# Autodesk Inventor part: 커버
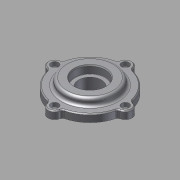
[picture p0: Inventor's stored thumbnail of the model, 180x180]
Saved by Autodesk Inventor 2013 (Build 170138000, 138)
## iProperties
Company: 한국ATC센터
Created: 2015-12
Part Number: 커버
Document SubType Name: Modeling
Designer: mdu
Density: 1 g/cm^3
Material: 일반
Mass: 49.9044 g
Surface Area: 145.431 cm^2
Volume: 49.9044 cm^3
Author: mdu
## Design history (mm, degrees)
sketch "스케치1"
  geometry: C1 r 1.621 at (0, 6.75) reference; C2 r 1.621 at (-37, -30.25) reference; C3 r 1.621 at (0, -67.25) reference; C4 r 1.621 at (37, -30.25) reference; C5 r 10 at (0, -30.25) reference; C6 r 12 at (0, -30.25); C7 r 24.5 at (0, -30.25) reference; A1 r 3 centre (-38.77, -20.408) between (-38.239, -23.361) and (-35.862, -21.146) reference; A2 r 7 centre (-37, -30.25) between (-38.239, -23.361) and (-38.239, -37.139) reference; A3 r 3 centre (-38.77, -40.092) between (-35.862, -39.354) and (-38.239, -37.139) reference; A4 r 37 centre (0, -30.25) between (-35.862, -39.354) and (-9.104, -66.113) reference; A5 r 3 centre (-9.842, -69.02) between (-6.889, -68.489) and (-9.104, -66.113) reference; A6 r 7 centre (0, -67.25) between (-6.889, -68.489) and (6.889, -68.489) reference; A7 r 3 centre (9.842, -69.02) between (9.104, -66.112) and (6.889, -68.489) reference; A8 r 37 centre (0, -30.25) between (9.104, -66.112) and (35.863, -39.354) reference; A9 r 3 centre (38.77, -40.092) between (38.239, -37.139) and (35.863, -39.354) reference; A10 r 7 centre (37, -30.25) between (38.239, -37.139) and (38.239, -23.361) reference; A11 r 3 centre (38.77, -20.408) between (35.863, -21.146) and (38.239, -23.361) reference; A12 r 37 centre (0, -30.25) between (35.863, -21.146) and (9.104, 5.612) reference; A13 r 3 centre (9.842, 8.52) between (6.889, 7.989) and (9.104, 5.612) reference; A14 r 7 centre (0, 6.75) between (6.889, 7.989) and (-6.889, 7.989) reference; A15 r 3 centre (-9.842, 8.52) between (-9.104, 5.612) and (-6.889, 7.989) reference; A16 r 37 centre (0, -30.25) between (-9.104, 5.612) and (-35.862, -21.146) reference; 1 further point
  constraints: 1 centre point, 1 coincident
  dimensions: "d2" = 2 radial gap between concentric circles of C6 C5
extrude "돌출1" new body sketch "스케치1" distance "d0" = 8; taper "d1" = 0 deg
sketch "스케치2"
  geometry: C1 r 23.5 at (0, -30.25) reference; C2 r 12 at (0, -30.25) reference; 1 further point
extrude "돌출2" join sketch "스케치2" distance "d4" = 5; taper "d5" = 0 deg
sketch "스케치3"
  geometry: C1 r 23.5 at (0, 0) reference; C2 r 20.5 at (0, 0); 1 further point
  constraints: 1 centre point
  dimensions: "d6" = 3 radial gap between concentric circles of C2 C1
node "작업 평면1"
extrude "돌출3" join sketch "스케치3" stored distance "d7" = 5; taper "d8" = 0 deg
fillet "모깎기1" dims "d9" = 3
sketch "스케치4"
  geometry: C1 r 12 at (0, -30.25) reference; C2 r 27 at (0, -30.25); 1 further point
  constraints: 1 centre point
  dimensions: "d10" = 15 radial gap between concentric circles of C1 C2
extrude "돌출4" join sketch "스케치4" distance "d11" = 7; taper "d12" = 0 deg
fillet "모깎기2" dims "d13" = 3
chamfer "모따기1" distance "d14" = 1; stored, may be unused: second distance "d15" = 2, angle "d16" = 45 deg
node "작업점1"
  node "작업축1"
chamfer "모따기2" distance "d24" = 1; stored, may be unused: second distance "d25" = 2, angle "d26" = 45 deg
hole "구멍6" diameter "d43" = 4.5; stored, may be unused: countersink angle "d47" = 90 deg, drill point angle "d49" = 118 deg; dims "d41" = 10, "d42" = 10, "d44" = 6, "d45" = 8, "d46" = 4.4, "d48" = 8
sketch "스케치8"
  geometry: C1 r 12 at (0, 0) reference; C2 r 16 at (0, 0); 1 further point
  constraints: 1 centre point, 1 coincident
  dimensions: "d53" = 32 diameter of C2
extrude "돌출5" cut sketch "스케치8" distance "d54" = 8.3; taper "d55" = 0 deg
fillet "모깎기3" dims "d56" = 0.3
chamfer "모따기3" distance "d57" = 1.2; stored, may be unused: second distance "d58" = 2, angle "d59" = 30 deg
node "솔리드1"
pattern_circular "원형 패턴1" dims angle "d51" = 360 deg
node "참조1"
node "참조2"
